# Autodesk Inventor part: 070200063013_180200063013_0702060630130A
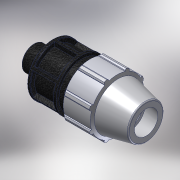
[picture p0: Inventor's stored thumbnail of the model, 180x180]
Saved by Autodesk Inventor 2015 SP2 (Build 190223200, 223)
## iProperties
Created: 2017-02
Part Number: 070200063013_180200063013_0702060630130A
Material: PVC-Piping
Description: PLASSON MALE ADAPTOR 63-1.1/4"
Document SubType Name: Modeling
Designer: KIM
Mass: 92.6774 g
Surface Area: 199.44 cm^2
Volume: 66.1981 cm^3
Density: 1.4 g/cm^3
Appearance: PTFE
Author: KIM
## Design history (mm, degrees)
derived "07020.ipt"
feature "Solid1::07020.ipt"
tag "TaggingFeature1"
body "Solid1"
other parameters: "d2" = 63, "d4" = 22, "d5" = 38.5, "d7" = 113, "d8" = 84.75, "d9" = 22, "d11" = 4.4, "d12" = 90.4, "d13" = 120 deg, "d14" = 88.2, "d15" = 6 deg, "d16" = 101.7, "d18" = 3.15, "d19" = 35 deg, "d20" = 17.5 deg, "d21" = 105.09, "d23" = 0, "d25" = 360 deg, "d27" = 2.26, "d34" = 5.65, "d36" = 0, "d42" = 38.5, "d43" = 3.39, "d46" = 1.89, "d49" = 123, "d51" = 154, "d52" = 22, "d53" = 1.26, "d55" = 360 deg, "d57" = 41.91, "d58" = 29.337, "d59" = 30.8, "d_" = 63, "E_" = 113, "H_" = 154, "l_" = 123, "l_2" = 22, "R_" = 41.91
